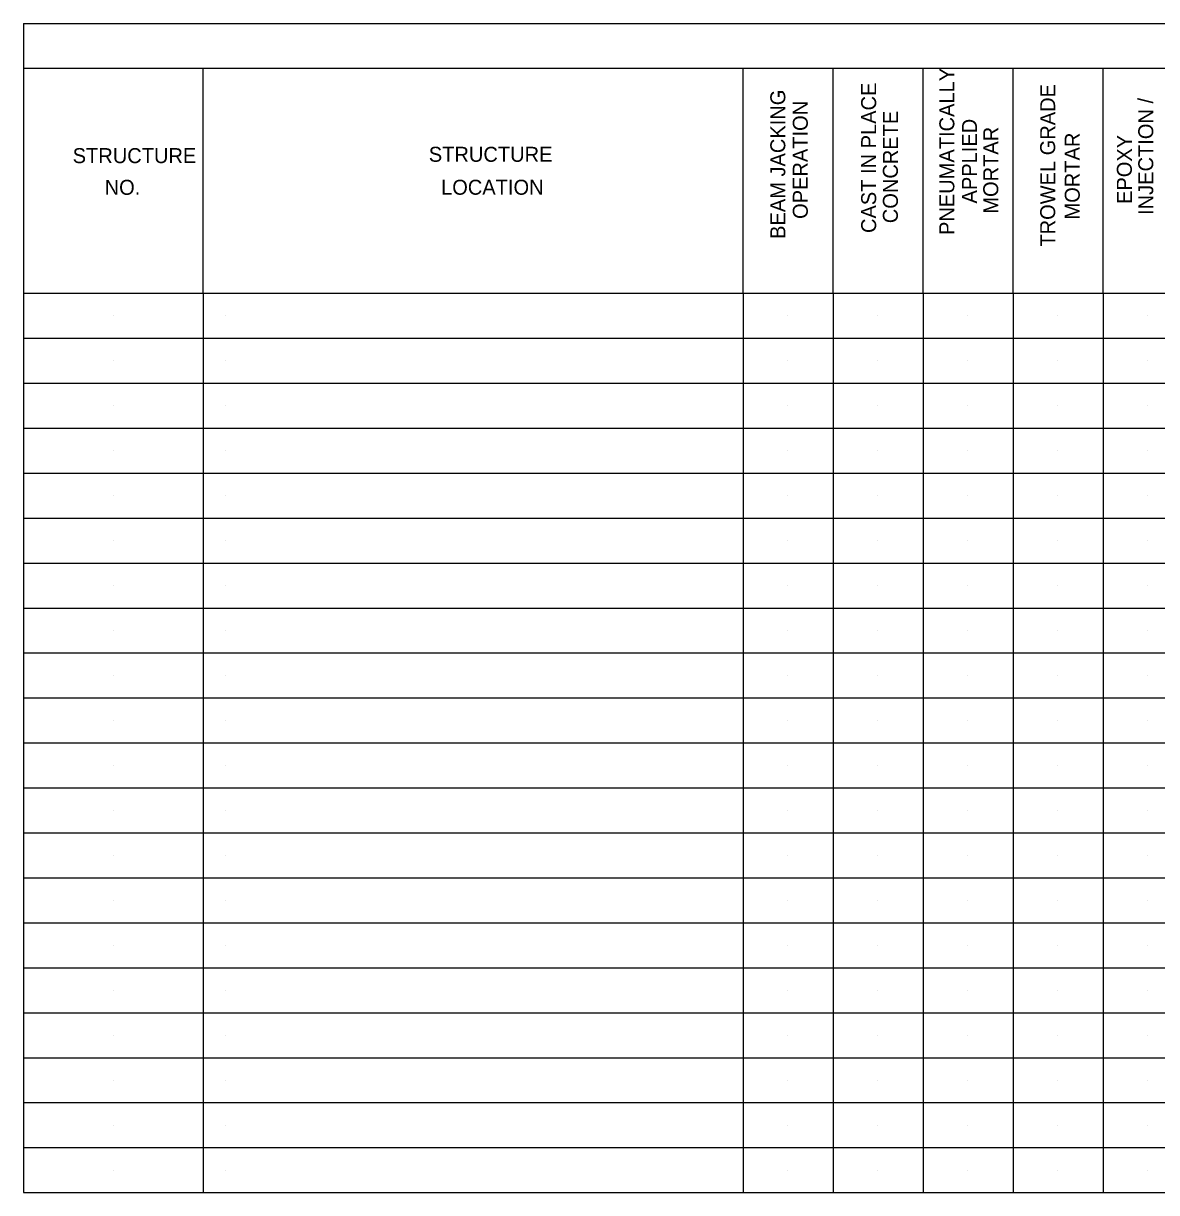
# Model space of a CAD drawing. Extents: x 3.4 to 29.9, y 7.8 to 20.1.
# Drawn here: x 3.42 to 15.32, y 7.79 to 20.08 of the extents above; entities that cross this region are included whole.
import ezdxf

# ---------------------------------------------------------------- set-up
doc = ezdxf.new("R2010")
doc.units = 0
doc.layers.add('G-ANNO-NOTE', color=7, linetype='Continuous')

msp = doc.modelspace()

# ---------------------------------------------------------------- linework, layer by layer
at = {"layer": 'G-ANNO-NOTE'}
for p, q in [((3.421, 20.077), (3.421, 7.794)), ((3.421, 20.077), (29.877, 20.077)), ((3.421, 19.605), (29.877, 19.605)), ((5.31, 17.242), (5.31, 19.605)), ((10.98, 17.242), (10.98, 19.605)), ((11.925, 17.242), (11.925, 19.605)), ((12.87, 17.242), (12.87, 19.605)), ((13.814, 17.242), (13.814, 19.605)), ((14.759, 17.242), (14.759, 19.605)), ((3.421, 17.242), (29.877, 17.242)), ((5.31, 17.242), (5.31, 7.794)), ((10.98, 17.242), (10.98, 7.794)), ((11.925, 17.242), (11.925, 7.794)), ((12.87, 17.242), (12.87, 7.794)), ((13.814, 17.242), (13.814, 7.794)), ((14.759, 17.242), (14.759, 7.794)), ((4.362, 17.006), (4.362, 17.006)), ((4.362, 17.006), (4.362, 17.006)), ((5.543, 17.006), (5.543, 17.006)), ((5.543, 17.006), (5.543, 17.006)), ((11.448, 17.006), (11.448, 17.006)), ((11.448, 17.006), (11.448, 17.006)), ((12.393, 17.006), (12.393, 17.006)), ((12.393, 17.006), (12.393, 17.006)), ((13.338, 17.006), (13.338, 17.006)), ((13.338, 17.006), (13.338, 17.006)), ((14.283, 17.006), (14.283, 17.006)), ((15.228, 17.006), (15.228, 17.006)), ((3.421, 16.77), (29.877, 16.77)), ((4.362, 16.534), (4.362, 16.534)), ((4.362, 16.534), (4.362, 16.534)), ((4.362, 16.534), (4.362, 16.534)), ((5.543, 16.534), (5.543, 16.534)), ((5.543, 16.534), (5.543, 16.534)), ((5.543, 16.534), (5.543, 16.534)), ((11.448, 16.534), (11.448, 16.534)), ((11.448, 16.534), (11.448, 16.534)), ((11.448, 16.534), (11.448, 16.534)), ((12.393, 16.534), (12.393, 16.534)), ((12.393, 16.534), (12.393, 16.534)), ((12.393, 16.534), (12.393, 16.534)), ((13.338, 16.534), (13.338, 16.534)), ((13.338, 16.534), (13.338, 16.534)), ((13.338, 16.534), (13.338, 16.534)), ((14.283, 16.534), (14.283, 16.534)), ((14.283, 16.534), (14.283, 16.534)), ((14.283, 16.534), (14.283, 16.534)), ((15.228, 16.534), (15.228, 16.534)), ((15.228, 16.534), (15.228, 16.534)), ((15.228, 16.534), (15.228, 16.534)), ((3.421, 16.298), (29.877, 16.298)), ((4.362, 16.061), (4.362, 16.061)), ((5.543, 16.061), (5.543, 16.061)), ((11.448, 16.061), (11.448, 16.061)), ((12.393, 16.061), (12.393, 16.061)), ((13.338, 16.061), (13.338, 16.061)), ((14.283, 16.061), (14.283, 16.061)), ((15.228, 16.061), (15.228, 16.061)), ((3.421, 15.825), (29.877, 15.825)), ((4.362, 15.589), (4.362, 15.589)), ((5.543, 15.589), (5.543, 15.589)), ((11.448, 15.589), (11.448, 15.589)), ((12.393, 15.589), (12.393, 15.589)), ((13.338, 15.589), (13.338, 15.589)), ((14.283, 15.589), (14.283, 15.589)), ((15.228, 15.589), (15.228, 15.589)), ((3.421, 15.353), (29.877, 15.353)), ((4.362, 15.116), (4.362, 15.116)), ((5.543, 15.116), (5.543, 15.116)), ((11.448, 15.116), (11.448, 15.116)), ((12.393, 15.116), (12.393, 15.116)), ((13.338, 15.116), (13.338, 15.116)), ((14.283, 15.116), (14.283, 15.116)), ((15.228, 15.116), (15.228, 15.116)), ((3.421, 14.88), (29.877, 14.88)), ((4.362, 14.644), (4.362, 14.644)), ((5.543, 14.644), (5.543, 14.644)), ((11.448, 14.644), (11.448, 14.644)), ((12.393, 14.644), (12.393, 14.644)), ((13.338, 14.644), (13.338, 14.644)), ((14.283, 14.644), (14.283, 14.644)), ((15.228, 14.644), (15.228, 14.644)), ((3.421, 14.408), (29.877, 14.408)), ((4.362, 14.172), (4.362, 14.172)), ((5.543, 14.172), (5.543, 14.172)), ((11.448, 14.172), (11.448, 14.172)), ((12.393, 14.172), (12.393, 14.172)), ((13.338, 14.172), (13.338, 14.172)), ((14.283, 14.172), (14.283, 14.172)), ((15.228, 14.172), (15.228, 14.172)), ((3.421, 13.935), (29.877, 13.935)), ((4.362, 13.699), (4.362, 13.699)), ((5.543, 13.699), (5.543, 13.699)), ((11.448, 13.699), (11.448, 13.699)), ((12.393, 13.699), (12.393, 13.699)), ((13.338, 13.699), (13.338, 13.699)), ((14.283, 13.699), (14.283, 13.699)), ((15.228, 13.699), (15.228, 13.699)), ((3.421, 13.463), (29.877, 13.463)), ((4.362, 13.227), (4.362, 13.227)), ((5.543, 13.227), (5.543, 13.227)), ((11.448, 13.227), (11.448, 13.227)), ((12.393, 13.227), (12.393, 13.227)), ((13.338, 13.227), (13.338, 13.227)), ((14.283, 13.227), (14.283, 13.227)), ((15.228, 13.227), (15.228, 13.227)), ((3.421, 12.991), (29.877, 12.991)), ((4.362, 12.754), (4.362, 12.754)), ((5.543, 12.754), (5.543, 12.754)), ((11.448, 12.754), (11.448, 12.754)), ((12.393, 12.754), (12.393, 12.754)), ((13.338, 12.754), (13.338, 12.754)), ((14.283, 12.754), (14.283, 12.754)), ((15.228, 12.754), (15.228, 12.754)), ((3.421, 12.518), (29.877, 12.518)), ((4.362, 12.282), (4.362, 12.282)), ((5.543, 12.282), (5.543, 12.282)), ((11.448, 12.282), (11.448, 12.282)), ((12.393, 12.282), (12.393, 12.282)), ((13.338, 12.282), (13.338, 12.282)), ((14.283, 12.282), (14.283, 12.282)), ((15.228, 12.282), (15.228, 12.282)), ((3.421, 12.046), (29.877, 12.046)), ((4.362, 11.809), (4.362, 11.809)), ((5.543, 11.809), (5.543, 11.809)), ((11.448, 11.809), (11.448, 11.809)), ((12.393, 11.809), (12.393, 11.809)), ((13.338, 11.809), (13.338, 11.809)), ((14.283, 11.809), (14.283, 11.809)), ((15.228, 11.809), (15.228, 11.809)), ((3.421, 11.573), (29.877, 11.573)), ((4.362, 11.337), (4.362, 11.337)), ((5.543, 11.337), (5.543, 11.337)), ((11.448, 11.337), (11.448, 11.337)), ((12.393, 11.337), (12.393, 11.337)), ((13.338, 11.337), (13.338, 11.337)), ((13.338, 11.337), (13.338, 11.337)), ((14.283, 11.337), (14.283, 11.337)), ((15.228, 11.337), (15.228, 11.337)), ((3.421, 11.101), (29.877, 11.101)), ((4.362, 10.864), (4.362, 10.864)), ((4.362, 10.864), (4.362, 10.864)), ((5.543, 10.864), (5.543, 10.864)), ((5.543, 10.864), (5.543, 10.864)), ((11.448, 10.864), (11.448, 10.864)), ((11.448, 10.864), (11.448, 10.864)), ((12.393, 10.864), (12.393, 10.864)), ((12.393, 10.864), (12.393, 10.864)), ((13.338, 10.864), (13.338, 10.864)), ((13.338, 10.864), (13.338, 10.864)), ((14.283, 10.864), (14.283, 10.864)), ((14.283, 10.864), (14.283, 10.864)), ((15.228, 10.864), (15.228, 10.864)), ((15.228, 10.864), (15.228, 10.864)), ((3.421, 10.628), (29.877, 10.628)), ((4.362, 10.392), (4.362, 10.392)), ((5.543, 10.392), (5.543, 10.392)), ((11.448, 10.392), (11.448, 10.392)), ((12.393, 10.392), (12.393, 10.392)), ((13.338, 10.392), (13.338, 10.392)), ((14.283, 10.392), (14.283, 10.392)), ((15.228, 10.392), (15.228, 10.392)), ((3.421, 10.156), (29.877, 10.156)), ((4.362, 9.92), (4.362, 9.92)), ((5.543, 9.92), (5.543, 9.92)), ((11.448, 9.92), (11.448, 9.92)), ((12.393, 9.92), (12.393, 9.92)), ((13.338, 9.92), (13.338, 9.92)), ((14.283, 9.92), (14.283, 9.92)), ((15.228, 9.92), (15.228, 9.92)), ((3.421, 9.683), (29.877, 9.683)), ((4.362, 9.447), (4.362, 9.447)), ((5.543, 9.447), (5.543, 9.447)), ((11.448, 9.447), (11.448, 9.447)), ((12.393, 9.447), (12.393, 9.447)), ((13.338, 9.447), (13.338, 9.447)), ((14.283, 9.447), (14.283, 9.447)), ((15.228, 9.447), (15.228, 9.447)), ((3.421, 9.211), (29.877, 9.211)), ((4.362, 8.975), (4.362, 8.975)), ((5.543, 8.975), (5.543, 8.975)), ((11.448, 8.975), (11.448, 8.975)), ((12.393, 8.975), (12.393, 8.975)), ((13.338, 8.975), (13.338, 8.975)), ((14.283, 8.975), (14.283, 8.975)), ((15.228, 8.975), (15.228, 8.975)), ((3.421, 8.739), (29.877, 8.739)), ((4.362, 8.502), (4.362, 8.502)), ((5.543, 8.502), (5.543, 8.502)), ((11.448, 8.502), (11.448, 8.502)), ((12.393, 8.502), (12.393, 8.502)), ((13.338, 8.502), (13.338, 8.502)), ((14.283, 8.502), (14.283, 8.502)), ((15.228, 8.502), (15.228, 8.502)), ((3.421, 8.266), (29.877, 8.266)), ((4.362, 8.03), (4.362, 8.03)), ((4.362, 8.03), (4.362, 8.03)), ((5.543, 8.03), (5.543, 8.03)), ((11.448, 8.03), (11.448, 8.03)), ((12.393, 8.03), (12.393, 8.03)), ((13.338, 8.03), (13.338, 8.03)), ((14.283, 8.03), (14.283, 8.03)), ((15.228, 8.03), (15.228, 8.03)), ((3.421, 7.794), (29.877, 7.794))]:
    msp.add_line(p, q, dxfattribs=at)

# ---------------------------------------------------------------- texts
for s, height, p in [('PNEUMATICALLY', 0.15748, (13.197, 17.854)), ('CAST IN PLACE', 0.15748, (12.376, 17.875)), ('TROWEL GRADE', 0.15748, (14.256, 17.732)), ('BEAM JACKING', 0.15748, (11.422, 17.813)), ('INJECTION /', 0.15748, (15.286, 18.065)), ('OPERATION', 0.1575, (11.658, 18.023)), ('CONCRETE', 0.1575, (12.604, 17.978)), ('APPLIED', 0.1575, (13.434, 18.185)), ('MORTAR', 0.1575, (13.658, 18.078)), ('MORTAR', 0.1575, (14.514, 18.017)), ('EPOXY', 0.1575, (15.061, 18.18))]:
    msp.add_text(s, height=height, rotation=90, dxfattribs=at).set_placement(p)
for s, p in [('STRUCTURE', (3.938, 18.609)), ('STRUCTURE', (7.678, 18.623)), ('NO.', (4.274, 18.276)), ('LOCATION', (7.807, 18.277))]:
    msp.add_text(s, height=0.1575, dxfattribs=at).set_placement(p)

doc.saveas('drawing.dxf')
